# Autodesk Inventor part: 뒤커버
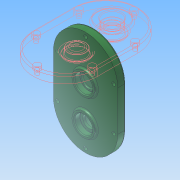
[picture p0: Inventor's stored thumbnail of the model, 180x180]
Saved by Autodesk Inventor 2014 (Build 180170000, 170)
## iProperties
Created: 2016-12
Part Number: 뒤커버
Material: 알루미늄 6061
Document SubType Name: Modeling
Designer: mduedu
Density: 2.71 g/cm^3
Appearance: 매끄러움 - 짙은 산림 녹색
Mass: 236.43 g
Surface Area: 240.701 cm^2
Volume: 87.2434 cm^3
Author: mduedu
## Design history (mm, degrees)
sketch "스케치1"
  geometry: L1 (40, -25)-(40, 25); L2 (-40, 25)-(-40, -25); L3 (-40, -25)-(40, 25); L4 (40, -25)-(-40, 25); A1 r 40 centre (0, 25) between (40, 25) and (-40, 25); A2 r 40 centre (0, -25) between (-40, -25) and (40, -25); 1 further point
  constraints: 8 end point, 4 point on circle, 4 tangent, 2 centre point, 2 midpoint, 1 parallel, 1 vertical
  dimensions: "d0" = 130 dimension on A2 A1; "d2" = 80 distance between parallel lines of L1 L2
extrude "돌출1" new body sketch "스케치1" distance "d3" = 10; taper "d4" = 0 deg
sketch "스케치2"
  geometry: C1 r 14 at (0, 11); 1 further point
  constraints: 1 centre point, 1 vertical alignment
  dimensions: "d5" = 28 diameter of C1; "d6" = 11 distance of C1.centre point (0, 0)
extrude "돌출2" join sketch "스케치2" distance "d7" = 3; taper "d8" = 0 deg
sketch "스케치3"
  geometry: C1 r 14 at (0, -33.1); C2 r 14 at (0, 11) reference; 1 further point
  constraints: 1 centre point, 1 vertical alignment
  dimensions: "d9" = 28 diameter of C1; "d69" = 44.1 distance of C1.centre C2.centre
extrude "돌출3" join sketch "스케치3" distance "d11" = 3; taper "d12" = 0 deg
hole "구멍1" diameter "d15" = 22; stored, may be unused: countersink angle "d19" = 90 deg, drill point angle "d21" = 0 deg; dims "d13" = 10, "d14" = 10, "d16" = 6, "d17" = 4, "d18" = 2, "d20" = 7
hole "구멍2" diameter "d24" = 18; stored, may be unused: countersink angle "d28" = 90 deg, drill point angle "d30" = 0 deg; dims "d22" = 10, "d23" = 10, "d25" = 6, "d26" = 4, "d27" = 2, "d29" = 1
hole "구멍3" diameter "d33" = 22; stored, may be unused: countersink angle "d37" = 90 deg, drill point angle "d39" = 0 deg; dims "d31" = 10, "d32" = 10, "d34" = 6, "d35" = 4, "d36" = 2, "d38" = 7
sketch "스케치4"
  geometry: C1 r 14 at (0, -33.1) reference; C2 r 18 at (0, -33.1); 1 further point
  constraints: 1 centre point, 1 coincident
  dimensions: "d40" = 36 diameter of C2
extrude "돌출4" join sketch "스케치4" distance "d41" = 4; taper "d42" = 0 deg
hole "구멍4" diameter "d45" = 22; stored, may be unused: countersink angle "d49" = 90 deg, drill point angle "d51" = 0 deg; dims "d43" = 10, "d44" = 10, "d46" = 6, "d47" = 4, "d48" = 2, "d50" = 7
hole "구멍5" diameter "d54" = 15; stored, may be unused: countersink angle "d58" = 90 deg, drill point angle "d60" = 0 deg; dims "d52" = 10, "d53" = 10, "d55" = 6, "d56" = 4, "d57" = 2, "d59" = 7
fillet "모깎기1" dims "d61" = 0.3
fillet "모깎기2" dims "d62" = 2
chamfer "모따기1" distance "d63" = 1; stored, may be unused: second distance "d64" = 2, angle "d65" = 45 deg
fillet "모깎기3" dims "d66" = 2
fillet "모깎기4" dims "d67" = 2
fillet "모깎기5" dims "d68" = 2
sketch "스케치5"
  geometry: L1 (-40, 25)-(-40, -25) reference; L2 (40, -25)-(40, 25) reference; L3 (35, 25)-(35, -25); L4 (-35, -25)-(-35, 25); A1 r 40 centre (0, 25) between (40, 25) and (-40, 25) reference; A2 r 40 centre (0, -25) between (-40, -25) and (40, -25) reference; A3 r 35 centre (0, 25) between (35, 25) and (-35, 25); A4 r 35 centre (0, -25) between (-35, -25) and (35, -25); 2 further points
  constraints: 5 point on circle, 4 end point, 2 centre point, 1 vertical alignment, 3 other
  dimensions: "d70" = 5 distance between parallel lines of L2 L3
sketch "스케치6"
  geometry: 1 further point
hole "구멍6" sketch "스케치6" at (0, 60) diameter "d71" = 4.5; stored, may be unused: countersink angle "d75" = 90 deg, drill point angle "d77" = 0 deg; dims "d72" = 6, "d73" = 8, "d74" = 4.6, "d76" = 8
node "솔리드1"
pattern_linear "직사각형 패턴1"
